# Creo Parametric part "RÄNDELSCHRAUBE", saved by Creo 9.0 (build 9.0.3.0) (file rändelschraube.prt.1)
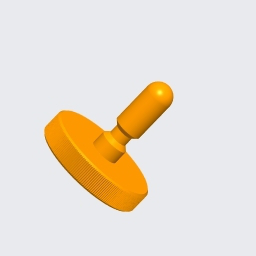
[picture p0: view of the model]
Units: millimeter Kilogram Sec (mmKs); MM, KILOGRAM, SECS
Materials in the file: STAHL

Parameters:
  WERKSTOFF = "Stahl"
  ERSTELLER = "ARINDA"
  BENENNUNG = "XXX"
  TEILETYP = "K"
  PTC_MASTER_MATERIAL = "STAHL"
  CLASS = "h"
  PLACEMENT = "EXTERNAL"

Other parameters: MASSE, MINOR_DIAMETER, PITCH

Created from: ARINDA_STARTTEIL.PRT

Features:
  1. coordinate system
  2. datum plane "RECHTS_Y-Z"
  3. datum plane "OBEN_X-Z"
  4. datum plane "VORNE_X-Y"
  5. datum axis
  6. datum axis
  7. datum axis
  8. datum point "PNT0"
  9. revolve "Drehen 1"
  10. revolved cut "Drehen 2"
  11. round "Rundung 1"
  12. feature "Kosmetisches Gewinde 1"
  13. chamfer "Fase 1"
  14. pattern "Muster 1"
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
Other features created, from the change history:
  coordinate system "CS1"
  extruded cut "Profil 1"
  extruded cut "Profil 1 [2]"
  extruded cut "Profil 1 [3]"
  extruded cut "Profil 1 [4]"
  extruded cut "Profil 1 [5]"
  extruded cut "Profil 1 [6]"
  extruded cut "Profil 1 [7]"
  extruded cut "Profil 1 [8]"
  extruded cut "Profil 1 [9]"
  extruded cut "Profil 1 [10]"
  extruded cut "Profil 1 [11]"
  extruded cut "Profil 1 [12]"
  extruded cut "Profil 1 [13]"
  extruded cut "Profil 1 [14]"
  extruded cut "Profil 1 [15]"
  extruded cut "Profil 1 [16]"
  extruded cut "Profil 1 [17]"
  extruded cut "Profil 1 [18]"
  extruded cut "Profil 1 [19]"
  extruded cut "Profil 1 [20]"
  extruded cut "Profil 1 [21]"
  extruded cut "Profil 1 [22]"
  extruded cut "Profil 1 [23]"
  extruded cut "Profil 1 [24]"
  extruded cut "Profil 1 [25]"
  extruded cut "Profil 1 [26]"
  extruded cut "Profil 1 [27]"
  extruded cut "Profil 1 [28]"
  extruded cut "Profil 1 [29]"
  extruded cut "Profil 1 [30]"
  extruded cut "Profil 1 [31]"
  extruded cut "Profil 1 [32]"
  extruded cut "Profil 1 [33]"
  extruded cut "Profil 1 [34]"
  extruded cut "Profil 1 [35]"
  extruded cut "Profil 1 [36]"
  extruded cut "Profil 1 [37]"
  extruded cut "Profil 1 [38]"
  extruded cut "Profil 1 [39]"
  extruded cut "Profil 1 [40]"
  extruded cut "Profil 1 [41]"
  extruded cut "Profil 1 [42]"
  extruded cut "Profil 1 [43]"
  extruded cut "Profil 1 [44]"
  extruded cut "Profil 1 [45]"
  extruded cut "Profil 1 [46]"
  extruded cut "Profil 1 [47]"
  extruded cut "Profil 1 [48]"
  extruded cut "Profil 1 [49]"
  extruded cut "Profil 1 [50]"
  extruded cut "Profil 1 [51]"
  extruded cut "Profil 1 [52]"
  extruded cut "Profil 1 [53]"
  extruded cut "Profil 1 [54]"
  extruded cut "Profil 1 [55]"
  extruded cut "Profil 1 [56]"
  extruded cut "Profil 1 [57]"
  extruded cut "Profil 1 [58]"
  extruded cut "Profil 1 [59]"
  extruded cut "Profil 1 [60]"
  extruded cut "Profil 1 [61]"
  extruded cut "Profil 1 [62]"
  extruded cut "Profil 1 [63]"
  extruded cut "Profil 1 [64]"
  extruded cut "Profil 1 [65]"
  extruded cut "Profil 1 [66]"
  extruded cut "Profil 1 [67]"
  extruded cut "Profil 1 [68]"
  extruded cut "Profil 1 [69]"
  extruded cut "Profil 1 [70]"
  extruded cut "Profil 1 [71]"
  extruded cut "Profil 1 [72]"
  extruded cut "Profil 1 [73]"
  extruded cut "Profil 1 [74]"
  extruded cut "Profil 1 [75]"
  extruded cut "Profil 1 [76]"
  extruded cut "Profil 1 [77]"
  extruded cut "Profil 1 [78]"
  extruded cut "Profil 1 [79]"
  extruded cut "Profil 1 [80]"
  extruded cut "Profil 1 [81]"
  extruded cut "Profil 1 [82]"
  extruded cut "Profil 1 [83]"
  extruded cut "Profil 1 [84]"
  extruded cut "Profil 1 [85]"
  extruded cut "Profil 1 [86]"
  extruded cut "Profil 1 [87]"
  extruded cut "Profil 1 [88]"
  extruded cut "Profil 1 [89]"
  extruded cut "Profil 1 [90]"
  extruded cut "Profil 1 [91]"
  extruded cut "Profil 1 [92]"
  extruded cut "Profil 1 [93]"
  extruded cut "Profil 1 [94]"
  extruded cut "Profil 1 [95]"
  extruded cut "Profil 1 [96]"
  extruded cut "Profil 1 [97]"
  extruded cut "Profil 1 [98]"
  extruded cut "Profil 1 [99]"
  extruded cut "Profil 1 [100]"
  extruded cut "Profil 1 [101]"
  extruded cut "Profil 1 [102]"
  extruded cut "Profil 1 [103]"
  extruded cut "Profil 1 [104]"
  extruded cut "Profil 1 [105]"
  extruded cut "Profil 1 [106]"
  extruded cut "Profil 1 [107]"
  extruded cut "Profil 1 [108]"
  extruded cut "Profil 1 [109]"
  extruded cut "Profil 1 [110]"
  extruded cut "Profil 1 [111]"
  extruded cut "Profil 1 [112]"
  extruded cut "Profil 1 [113]"
  extruded cut "Profil 1 [114]"
  extruded cut "Profil 1 [115]"
  extruded cut "Profil 1 [116]"
  extruded cut "Profil 1 [117]"
  extruded cut "Profil 1 [118]"
  extruded cut "Profil 1 [119]"
  extruded cut "Profil 1 [120]"
  extruded cut "Profil 1 [121]"
  extruded cut "Profil 1 [122]"
  extruded cut "Profil 1 [123]"
  extruded cut "Profil 1 [124]"
  extruded cut "Profil 1 [125]"
  extruded cut "Profil 1 [126]"
  extruded cut "Profil 1 [127]"
  extruded cut "Profil 1 [128]"
  extruded cut "Profil 1 [129]"
  extruded cut "Profil 1 [130]"
  extruded cut "Profil 1 [131]"
  extruded cut "Profil 1 [132]"
  extruded cut "Profil 1 [133]"
  extruded cut "Profil 1 [134]"
  extruded cut "Profil 1 [135]"
  extruded cut "Profil 1 [136]"
  extruded cut "Profil 1 [137]"
  extruded cut "Profil 1 [138]"
  extruded cut "Profil 1 [139]"
  extruded cut "Profil 1 [140]"
  extruded cut "Profil 1 [141]"
  extruded cut "Profil 1 [142]"
  extruded cut "Profil 1 [143]"
  extruded cut "Profil 1 [144]"
  extruded cut "Profil 1 [145]"
  extruded cut "Profil 1 [146]"
  extruded cut "Profil 1 [147]"
  extruded cut "Profil 1 [148]"
  extruded cut "Profil 1 [149]"
  extruded cut "Profil 1 [150]"
  extruded cut "Profil 1 [151]"
  extruded cut "Profil 1 [152]"
  extruded cut "Profil 1 [153]"
  extruded cut "Profil 1 [154]"
  extruded cut "Profil 1 [155]"
  extruded cut "Profil 1 [156]"
  extruded cut "Profil 1 [157]"
  extruded cut "Profil 1 [158]"
  extruded cut "Profil 1 [159]"
  extruded cut "Profil 1 [160]"
  extruded cut "Profil 1 [161]"
  extruded cut "Profil 1 [162]"
  extruded cut "Profil 1 [163]"
  extruded cut "Profil 1 [164]"
  extruded cut "Profil 1 [165]"
  extruded cut "Profil 1 [166]"
  extruded cut "Profil 1 [167]"
  extruded cut "Profil 1 [168]"
  extruded cut "Profil 1 [169]"
  extruded cut "Profil 1 [170]"
  extruded cut "Profil 1 [171]"
  extruded cut "Profil 1 [172]"
  extruded cut "Profil 1 [173]"
  extruded cut "Profil 1 [174]"
  extruded cut "Profil 1 [175]"
  extruded cut "Profil 1 [176]"
  extruded cut "Profil 1 [177]"
  extruded cut "Profil 1 [178]"
  extruded cut "Profil 1 [179]"
  extruded cut "Profil 1 [180]"

Other named items: RÄNDELSCHRAUBE, NUT, KOPF, RÄNDELUNG, A_X, A_Y, A_Z, CS0

Layers: 01_ACHSEN_STD, 01_EBENEN_STD, 01_KOORDSYS_STD, 01_PUNKTE_STD, GEWINDE, SAMMELFLÄCHEN, VOLUMENGEOMETRIE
